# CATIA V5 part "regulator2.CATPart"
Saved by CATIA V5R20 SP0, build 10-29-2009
Part number: r2
Bounding box of the stored display mesh (mm): x -16 to 16, y -16 to 16, z 0 to 32
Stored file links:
  C:\Users\khanm\Downloads\Catia Project\Catia Project\regulator2.CATPart
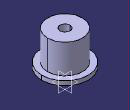
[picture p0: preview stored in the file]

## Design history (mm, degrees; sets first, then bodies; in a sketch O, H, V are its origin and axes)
Body1 (main body)
  Sketch1 on xy-plane, origin (0, 0, 0), H (1, 0, 0), V (0, 1, 0)
    circle A1 centre (0, 0) radius 1.5
    radius A1 = 1.5
  Pad1: profile Sketch1, direction (0, 0, 1), length 9
  Sketch2 on end face of Pad1, origin (0, 0, 9), H (1, 0, 0), V (0, 1, 0)
    circle A1 centre (0, 0) radius 16
    radius A1 = 16
  Pad2: profile Sketch2, direction (0, 0, 1), length 3
  Sketch3 on end face of Pad2, origin (0, 0, 12), H (1, 0, 0), V (0, 1, 0)
    circle A1 centre (0, 0) radius 12
    radius A1 = 12
  Pad3: profile Sketch3, direction (0, 0, 1), length 20
  Sketch4 on end face of Pad3, origin (0, 0, 32), H (1, 0, 0), V (0, 1, 0)
    circle A1 centre (0, 0) radius 3.5
    radius A1 = 3.5
  Pocket1: profile Sketch4, direction (0, 0, -1), length 20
